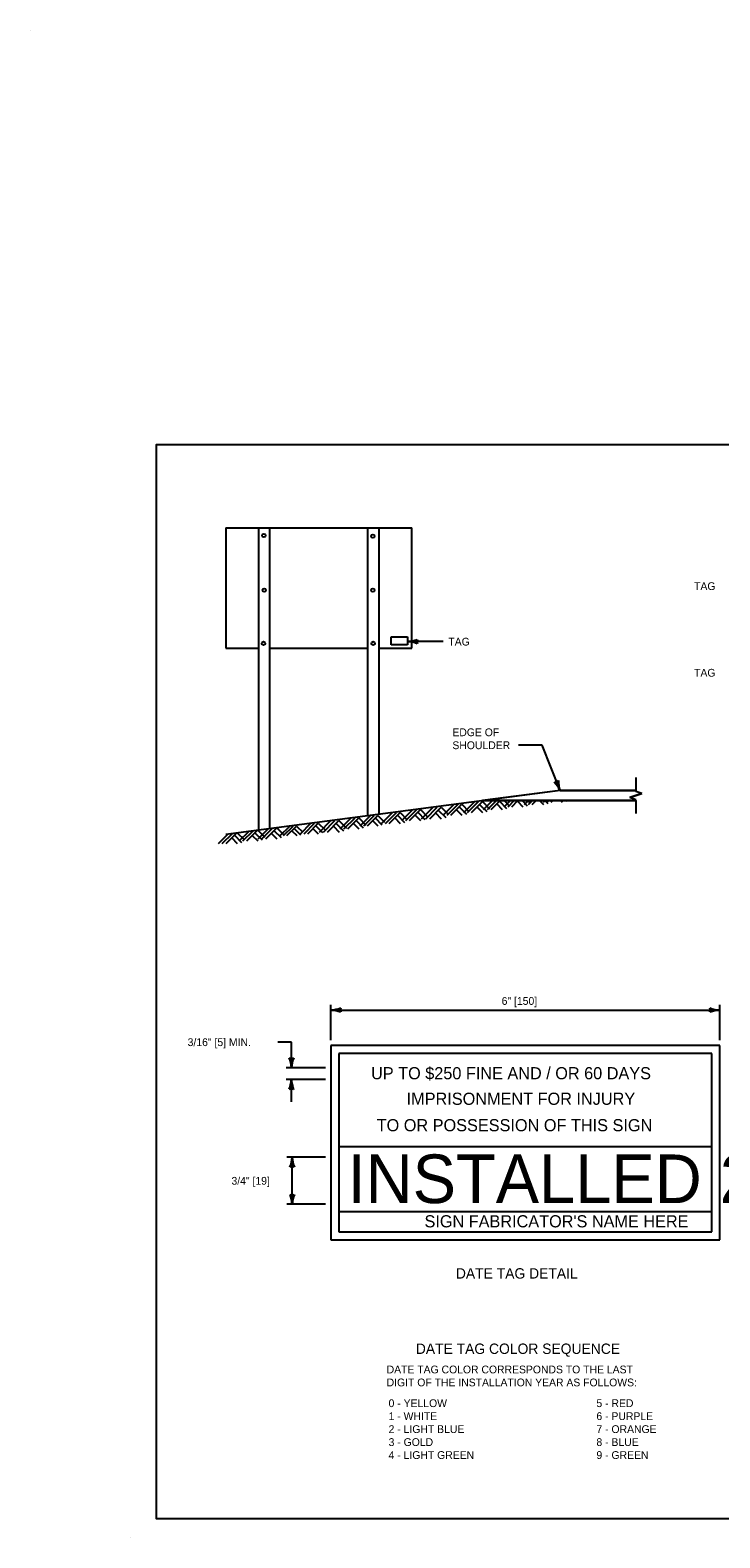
# Model space of a CAD drawing. Extents: x 49991.4 to 50021, y 49987.6 to 50011.4.
# Drawn here: x 50008.76 to 50014.08, y 49999.74 to 50011.36 of the extents above; entities that cross this region are included whole.
import ezdxf

# ---------------------------------------------------------------- set-up
doc = ezdxf.new("R2010")
doc.units = 0
for name, color, linetype in [('Level 1', 7, 'Continuous'), ('Level 2', 7, 'Continuous'), ('Level 3', 7, 'Continuous'), ('Level 6', 7, 'Continuous')]:
    doc.layers.add(name, color=color, linetype=linetype)

msp = doc.modelspace()

# ---------------------------------------------------------------- linework, layer by layer
at = {"layer": 'Level 1'}
for p, q in [((50008.765, 50011.363), (50008.765, 50011.363)), ((50010.274, 50007.524), (50011.708, 50007.524)), ((50010.274, 50007.524), (50010.274, 50006.596)), ((50010.527, 50005.194), (50010.527, 50007.524)), ((50010.527, 50007.524), (50010.611, 50007.524)), ((50010.611, 50007.524), (50010.611, 50005.205)), ((50011.37, 50005.305), (50011.37, 50007.524)), ((50011.37, 50007.524), (50011.455, 50007.524)), ((50011.455, 50007.524), (50011.455, 50005.316)), ((50011.708, 50006.596), (50011.708, 50007.524)), ((50011.548, 50006.622), (50011.548, 50006.685)), ((50011.548, 50006.685), (50011.674, 50006.685)), ((50011.674, 50006.622), (50011.548, 50006.622)), ((50011.674, 50006.685), (50011.674, 50006.622)), ((50010.274, 50006.596), (50010.526, 50006.596)), ((50010.611, 50006.596), (50011.37, 50006.596)), ((50011.455, 50006.596), (50011.708, 50006.596)), ((50012.851, 50005.499), (50010.274, 50005.161)), ((50012.851, 50005.499), (50012.254, 50005.421)), ((50012.851, 50005.499), (50013.435, 50005.499)), ((50013.435, 50005.499), (50012.851, 50005.499)), ((50013.389, 50005.444), (50013.435, 50005.46)), ((50013.435, 50005.492), (50013.435, 50005.499)), ((50013.481, 50005.476), (50013.435, 50005.492)), ((50013.435, 50005.46), (50013.481, 50005.476)), ((50011.632, 50005.267), (50011.716, 50005.352)), ((50011.661, 50005.267), (50011.746, 50005.352)), ((50011.691, 50005.267), (50011.775, 50005.352)), ((50011.775, 50005.352), (50011.83, 50005.297)), ((50011.783, 50005.281), (50011.872, 50005.37)), ((50011.815, 50005.281), (50011.903, 50005.37)), ((50011.846, 50005.281), (50011.934, 50005.37)), ((50011.912, 50005.348), (50011.97, 50005.29)), ((50011.934, 50005.37), (50011.992, 50005.313)), ((50011.951, 50005.309), (50012.035, 50005.393)), ((50011.98, 50005.309), (50012.065, 50005.393)), ((50012.01, 50005.309), (50012.094, 50005.393)), ((50012.053, 50005.351), (50012.095, 50005.309)), ((50012.074, 50005.372), (50012.129, 50005.317)), ((50012.094, 50005.393), (50012.149, 50005.338)), ((50012.109, 50005.329), (50012.193, 50005.413)), ((50012.138, 50005.329), (50012.223, 50005.413)), ((50012.168, 50005.329), (50012.252, 50005.413)), ((50012.211, 50005.371), (50012.253, 50005.329)), ((50012.231, 50005.392), (50012.286, 50005.338)), ((50012.252, 50005.413), (50012.307, 50005.358)), ((50013.435, 50005.421), (50012.254, 50005.421)), ((50012.254, 50005.421), (50012.736, 50005.421)), ((50012.262, 50005.352), (50012.33, 50005.421)), ((50012.291, 50005.352), (50012.36, 50005.421)), ((50012.321, 50005.352), (50012.389, 50005.421)), ((50012.363, 50005.395), (50012.406, 50005.352)), ((50012.385, 50005.416), (50012.439, 50005.361)), ((50012.421, 50005.421), (50012.46, 50005.382)), ((50012.421, 50005.373), (50012.468, 50005.421)), ((50012.45, 50005.373), (50012.498, 50005.421)), ((50012.48, 50005.373), (50012.527, 50005.421)), ((50012.522, 50005.416), (50012.565, 50005.373)), ((50012.56, 50005.421), (50012.598, 50005.382)), ((50012.578, 50005.39), (50012.609, 50005.421)), ((50012.601, 50005.421), (50012.619, 50005.403)), ((50012.608, 50005.39), (50012.639, 50005.421)), ((50012.637, 50005.39), (50012.668, 50005.421)), ((50012.692, 50005.421), (50012.723, 50005.39)), ((50012.723, 50005.408), (50012.736, 50005.421)), ((50012.734, 50005.421), (50012.756, 50005.398)), ((50012.735, 50005.419), (50012.734, 50005.421)), ((50012.734, 50005.421), (50013.435, 50005.421)), ((50012.736, 50005.421), (50012.735, 50005.419)), ((50012.753, 50005.408), (50012.766, 50005.421)), ((50012.775, 50005.421), (50012.777, 50005.419)), ((50012.782, 50005.408), (50012.795, 50005.421)), ((50012.854, 50005.421), (50012.867, 50005.408)), ((50012.896, 50005.421), (50012.901, 50005.416)), ((50013.435, 50005.427), (50013.389, 50005.444)), ((50013.435, 50005.421), (50013.435, 50005.427)), ((50010.693, 50005.151), (50010.767, 50005.225)), ((50010.719, 50005.151), (50010.794, 50005.225)), ((50010.745, 50005.151), (50010.82, 50005.225)), ((50010.82, 50005.225), (50010.868, 50005.177)), ((50010.849, 50005.166), (50010.93, 50005.247)), ((50010.877, 50005.166), (50010.958, 50005.247)), ((50010.906, 50005.166), (50010.986, 50005.247)), ((50010.967, 50005.227), (50011.019, 50005.175)), ((50010.986, 50005.247), (50011.039, 50005.195)), ((50010.996, 50005.178), (50011.084, 50005.267)), ((50011.027, 50005.178), (50011.115, 50005.267)), ((50011.058, 50005.178), (50011.146, 50005.267)), ((50011.103, 50005.223), (50011.147, 50005.178)), ((50011.125, 50005.245), (50011.182, 50005.188)), ((50011.146, 50005.267), (50011.204, 50005.209)), ((50011.156, 50005.203), (50011.24, 50005.288)), ((50011.185, 50005.203), (50011.27, 50005.288)), ((50011.215, 50005.203), (50011.299, 50005.288)), ((50011.257, 50005.246), (50011.3, 50005.203)), ((50011.278, 50005.267), (50011.333, 50005.212)), ((50011.299, 50005.288), (50011.354, 50005.233)), ((50011.309, 50005.227), (50011.39, 50005.307)), ((50011.337, 50005.227), (50011.418, 50005.307)), ((50011.366, 50005.227), (50011.445, 50005.307)), ((50011.406, 50005.268), (50011.446, 50005.227)), ((50011.426, 50005.287), (50011.478, 50005.235)), ((50011.445, 50005.307), (50011.498, 50005.255)), ((50011.475, 50005.245), (50011.559, 50005.329)), ((50011.504, 50005.245), (50011.589, 50005.329)), ((50011.534, 50005.245), (50011.618, 50005.329)), ((50011.577, 50005.288), (50011.619, 50005.245)), ((50011.597, 50005.308), (50011.652, 50005.253)), ((50011.618, 50005.329), (50011.673, 50005.274)), ((50011.733, 50005.31), (50011.776, 50005.267)), ((50011.754, 50005.331), (50011.809, 50005.276)), ((50011.89, 50005.326), (50011.935, 50005.281)), ((50010.217, 50005.09), (50010.29, 50005.163)), ((50010.246, 50005.09), (50010.324, 50005.168)), ((50010.276, 50005.09), (50010.358, 50005.172)), ((50010.319, 50005.133), (50010.361, 50005.09)), ((50010.34, 50005.154), (50010.394, 50005.099)), ((50010.362, 50005.173), (50010.415, 50005.12)), ((50010.376, 50005.11), (50010.45, 50005.184)), ((50010.405, 50005.11), (50010.484, 50005.189)), ((50010.435, 50005.11), (50010.518, 50005.193)), ((50010.477, 50005.152), (50010.52, 50005.11)), ((50010.498, 50005.173), (50010.553, 50005.118)), ((50010.52, 50005.193), (50010.574, 50005.139)), ((50010.523, 50005.127), (50010.599, 50005.204)), ((50010.552, 50005.127), (50010.633, 50005.208)), ((50010.582, 50005.127), (50010.666, 50005.212)), ((50010.624, 50005.17), (50010.667, 50005.127)), ((50010.645, 50005.191), (50010.7, 50005.136)), ((50010.666, 50005.212), (50010.721, 50005.157)), ((50010.783, 50005.188), (50010.821, 50005.151)), ((50010.801, 50005.207), (50010.85, 50005.158)), ((50010.946, 50005.207), (50010.987, 50005.166)), ((50014.083, 50003.533), (50011.083, 50003.533)), ((50011.083, 50003.533), (50011.083, 50002.033)), ((50014.083, 50002.033), (50014.083, 50003.533)), ((50014.021, 50003.471), (50011.146, 50003.471)), ((50011.146, 50003.471), (50011.146, 50002.096)), ((50014.021, 50002.096), (50014.021, 50003.471)), ((50014.021, 50002.752), (50011.146, 50002.752)), ((50011.146, 50002.252), (50014.021, 50002.252)), ((50011.146, 50002.096), (50014.021, 50002.096)), ((50011.083, 50002.033), (50014.083, 50002.033)), ((50009.537, 49999.736), (50009.537, 49999.736))]:
    msp.add_line(p, q, dxfattribs=at)
msp.add_lwpolyline([(50020.938, 50008.165), (50009.737, 50008.165), (50009.737, 49999.886), (50020.938, 49999.886)], close=True, dxfattribs=at)
for centre in [(50010.567, 50007.466), (50011.407, 50007.46), (50010.57, 50007.044), (50011.407, 50007.044), (50010.564, 50006.634), (50011.41, 50006.634)]:
    msp.add_circle(centre, 0.0135, dxfattribs=at)
at = {"layer": 'Level 3'}
for p, q in [((50011.95, 50006.647), (50011.674, 50006.647)), ((50012.713, 50005.848), (50012.532, 50005.848)), ((50012.851, 50005.499), (50012.713, 50005.848)), ((50011.083, 50003.573), (50011.083, 50003.846)), ((50014.083, 50003.573), (50014.083, 50003.846)), ((50011.083, 50003.806), (50014.083, 50003.806)), ((50010.78, 50003.558), (50010.674, 50003.558)), ((50010.78, 50003.361), (50010.78, 50003.558)), ((50011.043, 50003.361), (50010.74, 50003.361)), ((50011.043, 50003.271), (50010.739, 50003.271)), ((50010.779, 50003.097), (50010.779, 50003.271)), ((50011.043, 50002.671), (50010.745, 50002.671)), ((50010.785, 50002.308), (50010.785, 50002.671)), ((50011.043, 50002.308), (50010.745, 50002.308))]:
    msp.add_line(p, q, dxfattribs=at)
for centre, radius, start, end in [((50011.665, 50006.425), 0.222, 67.439, 87.6226), ((50011.663, 50006.88), 0.233, 272.8103, 292.0602), ((50011.803, 50006.647), 0.0548, 162.1219, 197.8442), ((50012.804, 50005.618), 0.0548, 273.614, 309.3363), ((50013.061, 50005.572), 0.222, 178.9312, 199.1147), ((50012.638, 50005.403), 0.233, 24.3025, 43.5523), ((50011.072, 50004.039), 0.233, 272.8273, 292.0772), ((50011.212, 50003.806), 0.0548, 162.1388, 197.8612), ((50014.092, 50004.028), 0.222, 247.456, 267.6395), ((50013.955, 50003.806), 0.0548, 342.1388, 17.8612), ((50011.074, 50003.584), 0.222, 67.456, 87.6395), ((50014.095, 50003.573), 0.233, 92.8273, 112.0772), ((50010.78, 50003.49), 0.0548, 252.1388, 287.8612), ((50010.547, 50003.35), 0.233, 2.8273, 22.0772), ((50011.002, 50003.352), 0.222, 157.456, 177.6395), ((50010.557, 50003.28), 0.222, 337.456, 357.6395), ((50011.012, 50003.282), 0.233, 182.8273, 202.0772), ((50010.779, 50003.142), 0.0548, 72.1388, 107.8612), ((50010.563, 50002.68), 0.222, 337.456, 357.6395), ((50011.018, 50002.682), 0.233, 182.8273, 202.0772), ((50010.785, 50002.542), 0.0548, 72.1388, 107.8612), ((50010.785, 50002.436), 0.0548, 252.1388, 287.8612), ((50010.553, 50002.297), 0.233, 2.8273, 22.0772), ((50011.008, 50002.299), 0.222, 157.456, 177.6395)]:
    msp.add_arc(centre, radius, start, end, dxfattribs=at)
at = {"layer": 'Level 6'}
for p, q in [((50013.435, 50005.599), (50013.435, 50005.492)), ((50013.435, 50005.46), (50013.389, 50005.444)), ((50013.481, 50005.476), (50013.435, 50005.492)), ((50013.481, 50005.476), (50013.435, 50005.46)), ((50013.435, 50005.427), (50013.389, 50005.444)), ((50013.435, 50005.421), (50013.435, 50005.321))]:
    msp.add_line(p, q, dxfattribs=at)

# ---------------------------------------------------------------- texts
at = {"layer": 'Level 1'}
for s, height, p in [('UP TO $250 FINE AND / OR 60 DAYS', 0.0937, (50011.394, 50003.272)), ('IMPRISONMENT FOR INJURY', 0.0938, (50011.668, 50003.075)), ('TO OR POSSESSION OF THIS SIGN', 0.0938, (50011.437, 50002.871)), ('INSTALLED 2010', 0.375, (50011.213, 50002.317)), ("SIGN FABRICATOR'S NAME HERE", 0.0937, (50011.806, 50002.13))]:
    msp.add_text(s, height=height, dxfattribs=at).set_placement(p)
at = {"layer": 'Level 2'}
for s, height, p in [('TAG', 0.06, (50013.885, 50007.045)), ('TAG', 0.06, (50011.99, 50006.617)), ('TAG', 0.06, (50013.885, 50006.377)), ('EDGE OF', 0.06, (50012.021, 50005.918)), ('SHOULDER', 0.06, (50012.021, 50005.818)), ('6" [150]', 0.06, (50012.401, 50003.846)), (' 3/16" [5] MIN.', 0.06, (50009.957, 50003.528)), (' 3/4" [19]', 0.06, (50010.295, 50002.459)), ('DATE TAG DETAIL', 0.08, (50012.048, 50001.735)), ('DATE TAG COLOR SEQUENCE', 0.08, (50011.739, 50001.154)), ('DATE TAG COLOR CORRESPONDS TO THE LAST', 0.06, (50011.514, 50001.004)), ('DIGIT OF THE INSTALLATION YEAR AS FOLLOWS:', 0.06, (50011.514, 50000.904)), ('0 - YELLOW', 0.06, (50011.529, 50000.744)), ('5 - RED', 0.06, (50013.132, 50000.744)), ('1 - WHITE', 0.06, (50011.529, 50000.644)), ('6 - PURPLE', 0.06, (50013.132, 50000.644)), ('2 - LIGHT BLUE', 0.06, (50011.529, 50000.544)), ('7 - ORANGE', 0.06, (50013.132, 50000.544)), ('3 - GOLD', 0.06, (50011.529, 50000.444)), ('8 - BLUE', 0.06, (50013.132, 50000.444)), ('4 - LIGHT GREEN', 0.06, (50011.529, 50000.344)), ('9 - GREEN', 0.06, (50013.132, 50000.344))]:
    msp.add_text(s, height=height, dxfattribs=at).set_placement(p)

doc.saveas('drawing.dxf')
